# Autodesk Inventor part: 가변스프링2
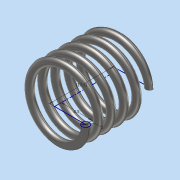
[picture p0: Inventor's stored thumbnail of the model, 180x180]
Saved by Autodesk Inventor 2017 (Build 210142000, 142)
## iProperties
Part Number: 가변스프링2
Material: 스테인레스 스틸
Document SubType Name: Modeling
Designer: MRC
Density: 8 g/cm^3
Appearance: 반연마
Mass: 6.54895 g
Surface Area: 16.6959 cm^2
Volume: 0.818619 cm^3
Author: MRC
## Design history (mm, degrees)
sketch "스케치1"
  geometry: L1 (0, 0)-(0, 17.5); L2 (0, 0)-(8.5, 0); L3 (0, 17.5)-(8.5, 17.5); C1 r 1 at (8.5, 0)
  constraints: 6 end point, 2 horizontal, 1 centre point, 1 coincident, 1 vertical
  dimensions: "d0" = 17.5 distance of L1.start L1.end (derived); "d1" = 8.5 distance of L1.start L2.end; "d2" = 2 diameter of C1
feature "코일1" pitch "d3" = 10; turns "d5" = 5; dims "d4" = 17.5 (= d0), "d6" = 0, angle "d7" = 90 deg, angle "d8" = 90 deg, "d9" = 0, "d10" = 0
sketch "스케치2"
  geometry: L1 (17.5, 13.489)-(0, 13.489); L2 (0, 13.489)-(0, -13.489); L3 (0, -13.489)-(17.5, -13.489); L4 (17.5, -13.489)-(17.5, 13.489); 2 further points
  constraints: 8 end point, 2 parallel, 1 coincident, 1 horizontal, 1 midpoint, 1 perpendicular
  dimensions: "d11" = 17.5 distance of L2.end L3.end (= d0)
extrude "돌출1" sketch "스케치2" stored distance "d12" = 0; taper "d13" = 0 deg
node "솔리드1"
